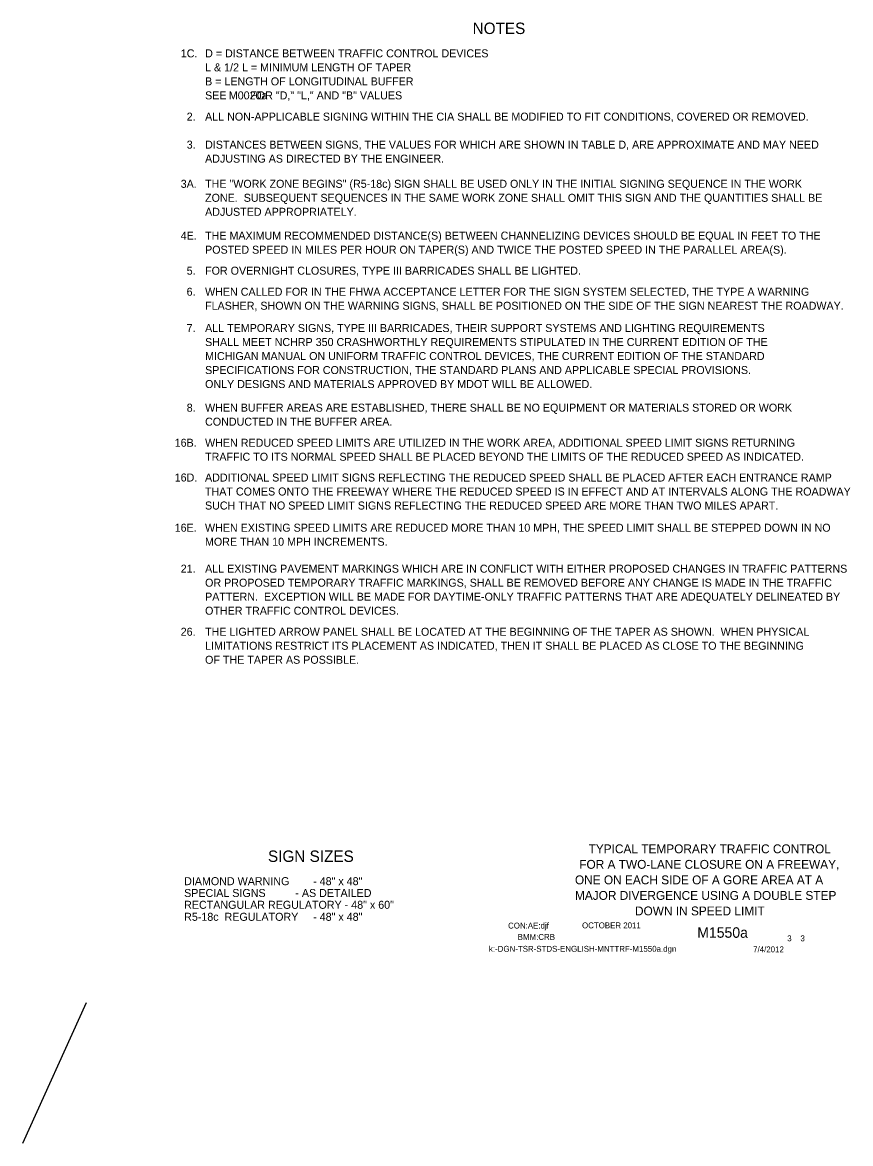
# Model space of a CAD drawing. Extents: x 16452 to 19508, y 5713 to 7079.
# Drawn here: x 18639 to 19508, y 5732 to 6909 of the extents above; entities that cross this region are included whole.
import ezdxf

# ---------------------------------------------------------------- set-up
doc = ezdxf.new("R2010")
doc.units = 0
for name, color, linetype in [('BORDER', 7, 'Continuous'), ('BORDER_SIGNAL_WO', 7, 'Continuous'), ('TYPICAL_TEXT_DIMEN_PR', 7, 'Continuous')]:
    doc.layers.add(name, color=color, linetype=linetype)

msp = doc.modelspace()

# ---------------------------------------------------------------- linework, layer by layer
at = {"layer": 'TYPICAL_TEXT_DIMEN_PR'}
msp.add_line((18705.8, 5880), (18639, 5732.4), dxfattribs=at)

# ---------------------------------------------------------------- texts
at = {"layer": 'BORDER'}
for s, p in [('TYPICAL TEMPORARY TRAFFIC CONTROL', (19233.2, 6037.1)), ('FOR A TWO-LANE CLOSURE ON A FREEWAY,', (19223.4, 6020.8)), ('ONE ON EACH SIDE OF A GORE AREA AT A ', (19218.9, 6004.5)), ('MAJOR DIVERGENCE USING A DOUBLE STEP ', (19218.9, 5988.2)), ('DOWN IN SPEED LIMIT', (19281.9, 5971.9))]:
    msp.add_text(s, height=9.3, dxfattribs=at).set_placement(p)
at = {"layer": 'BORDER_SIGNAL_WO'}
for s, height, p in [('CON:AE:djf  ', 6.2, (19148.7, 5958.1)), ('    OCTOBER 2011    ', 6.2, (19217.1, 5958.3)), ('    M1550a   ', 11, (19330.9, 5948.4)), ('BMM:CRB   ', 6.2, (19158.8, 5946.2)), (' 3    3 ', 6.2, (19439.4, 5944.7)), ('k:-DGN-TSR-STDS-ENGLISH-MNTTRF-M1550a.dgn      ', 6.2, (19128.6, 5933.7)), ('7/4/2012      ', 6.2, (19405.9, 5933.1))]:
    msp.add_text(s, height=height, dxfattribs=at).set_placement(p)
at = {"layer": 'TYPICAL_TEXT_DIMEN_PR'}
for s, height, p in [('NOTES', 12, (19111.5, 6897)), ('1C.', 8.4, (18805.2, 6872.5)), ('D = DISTANCE BETWEEN TRAFFIC CONTROL DEVICES', 8.4, (18830.7, 6872.5)), ('L & 1/2 L = MINIMUM LENGTH OF TAPER', 8.4, (18830.7, 6857.8)), ('B = LENGTH OF LONGITUDINAL BUFFER', 8.4, (18830.7, 6843.1)), ('SEE        FOR "D," "L," AND "B" VALUES', 8.4, (18830.7, 6828.4)), ('M0020a', 8.4, (18855.6, 6828.4)), ('2.', 8.4, (18811.4, 6806.1)), ('ALL NON-APPLICABLE SIGNING WITHIN THE CIA SHALL BE MODIFIED TO FIT CONDITIONS, COVERED OR REMOVED.', 8.4, (18830.7, 6806.1)), ('3.', 8.4, (18811.4, 6776.7)), ('DISTANCES BETWEEN SIGNS, THE VALUES FOR WHICH ARE SHOWN IN TABLE D, ARE APPROXIMATE AND MAY NEED', 8.4, (18830.7, 6776.7)), ('ADJUSTING AS DIRECTED BY THE ENGINEER.', 8.4, (18830.7, 6762)), ('3A.', 8.4, (18805.1, 6735.6)), ('THE "WORK ZONE BEGINS" (R5-18c) SIGN SHALL BE USED ONLY IN THE INITIAL SIGNING SEQUENCE IN THE WORK', 8.4, (18830.7, 6735.6)), ('ZONE.  SUBSEQUENT SEQUENCES IN THE SAME WORK ZONE SHALL OMIT THIS SIGN AND THE QUANTITIES SHALL BE', 8.4, (18830.7, 6720.9)), ('ADJUSTED APPROPRIATELY.', 8.4, (18830.7, 6706.2)), ('4E.', 8.4, (18805.1, 6681.2)), ('THE MAXIMUM RECOMMENDED DISTANCE(S) BETWEEN CHANNELIZING DEVICES SHOULD BE EQUAL IN FEET TO THE', 8.4, (18830.7, 6681.2)), ('POSTED SPEED IN MILES PER HOUR ON TAPER(S) AND TWICE THE POSTED SPEED IN THE PARALLEL AREA(S).', 8.4, (18830.7, 6666.4)), ('5.', 8.4, (18811.4, 6644.4)), ('FOR OVERNIGHT CLOSURES, TYPE III BARRICADES SHALL BE LIGHTED. ', 8.4, (18830.7, 6644.4)), ('6.', 8.4, (18811.3, 6622.3)), ('WHEN CALLED FOR IN THE FHWA ACCEPTANCE LETTER FOR THE SIGN SYSTEM SELECTED, THE TYPE A WARNING ', 8.4, (18830.7, 6622.3)), ('FLASHER, SHOWN ON THE WARNING SIGNS, SHALL BE POSITIONED ON THE SIDE OF THE SIGN NEAREST THE ROADWAY.', 8.4, (18830.7, 6607.6)), ('7.', 8.4, (18811.3, 6584.2)), ('ALL TEMPORARY SIGNS, TYPE III BARRICADES, THEIR SUPPORT SYSTEMS AND LIGHTING REQUIREMENTS', 8.4, (18830.7, 6584.2)), ('SHALL MEET NCHRP 350 CRASHWORTHLY REQUIREMENTS STIPULATED IN THE CURRENT EDITION OF THE', 8.4, (18830.7, 6569.5)), ('MICHIGAN MANUAL ON UNIFORM TRAFFIC CONTROL DEVICES, THE CURRENT EDITION OF THE STANDARD', 8.4, (18830.7, 6554.8)), ('SPECIFICATIONS FOR CONSTRUCTION, THE STANDARD PLANS AND APPLICABLE SPECIAL PROVISIONS.', 8.4, (18830.7, 6540.1)), ('ONLY DESIGNS AND MATERIALS APPROVED BY MDOT WILL BE ALLOWED.', 8.4, (18830.7, 6525.4)), ('8.', 8.4, (18811.4, 6500.6)), ('WHEN BUFFER AREAS ARE ESTABLISHED, THERE SHALL BE NO EQUIPMENT OR MATERIALS STORED OR WORK     ', 8.4, (18830.7, 6500.6)), ('CONDUCTED IN THE BUFFER AREA.', 8.4, (18830.7, 6485.9)), ('16B.', 8.4, (18798.8, 6463.8)), ('WHEN REDUCED SPEED LIMITS ARE UTILIZED IN THE WORK AREA, ADDITIONAL SPEED LIMIT SIGNS RETURNING', 8.4, (18830.7, 6463.8)), ('TRAFFIC TO ITS NORMAL SPEED SHALL BE PLACED BEYOND THE LIMITS OF THE REDUCED SPEED AS INDICATED.', 8.4, (18830.7, 6449.1)), ('16D.', 8.4, (18798.8, 6427.3)), ('ADDITIONAL SPEED LIMIT SIGNS REFLECTING THE REDUCED SPEED SHALL BE PLACED AFTER EACH ENTRANCE RAMP', 8.4, (18830.6, 6427.3)), ('THAT COMES ONTO THE FREEWAY WHERE THE REDUCED SPEED IS IN EFFECT AND AT INTERVALS ALONG THE ROADWAY', 8.4, (18830.6, 6412.6)), ('SUCH THAT NO SPEED LIMIT SIGNS REFLECTING THE REDUCED SPEED ARE MORE THAN TWO MILES APART.', 8.4, (18830.6, 6397.9)), ('16E.', 8.4, (18798.8, 6374.6)), ('WHEN EXISTING SPEED LIMITS ARE REDUCED MORE THAN 10 MPH, THE SPEED LIMIT SHALL BE STEPPED DOWN IN NO', 8.4, (18830.6, 6374.6)), ('MORE THAN 10 MPH INCREMENTS.', 8.4, (18830.6, 6359.9)), ('21.', 8.4, (18805.1, 6331.6)), ('ALL EXISTING PAVEMENT MARKINGS WHICH ARE IN CONFLICT WITH EITHER PROPOSED CHANGES IN TRAFFIC PATTERNS', 8.4, (18830.7, 6331.6)), ('OR PROPOSED TEMPORARY TRAFFIC MARKINGS, SHALL BE REMOVED BEFORE ANY CHANGE IS MADE IN THE TRAFFIC', 8.4, (18830.7, 6316.9)), ('PATTERN.  EXCEPTION WILL BE MADE FOR DAYTIME-ONLY TRAFFIC PATTERNS THAT ARE ADEQUATELY DELINEATED BY', 8.4, (18830.7, 6302.2)), ('OTHER TRAFFIC CONTROL DEVICES.', 8.4, (18830.7, 6287.5)), ('26.', 8.4, (18805.1, 6265.4)), ('THE LIGHTED ARROW PANEL SHALL BE LOCATED AT THE BEGINNING OF THE TAPER AS SHOWN.  WHEN PHYSICAL', 8.4, (18830.7, 6265.4)), ('LIMITATIONS RESTRICT ITS PLACEMENT AS INDICATED, THEN IT SHALL BE PLACED AS CLOSE TO THE BEGINNING', 8.4, (18830.7, 6250.7)), ('OF THE TAPER AS POSSIBLE.', 8.4, (18830.7, 6236)), ('SIGN SIZES', 12, (18896.7, 6028)), ('DIAMOND WARNING        - 48" x 48"', 8.4, (18808.7, 6003.6)), ('SPECIAL SIGNS          - AS DETAILED', 8.4, (18808.7, 5991.2)), ('RECTANGULAR REGULATORY - 48" x 60"', 8.4, (18808.7, 5978.8)), ('R5-18c  REGULATORY     - 48" x 48"', 8.4, (18808.7, 5966.2))]:
    msp.add_text(s, height=height, dxfattribs=at).set_placement(p)

doc.saveas('drawing.dxf')
